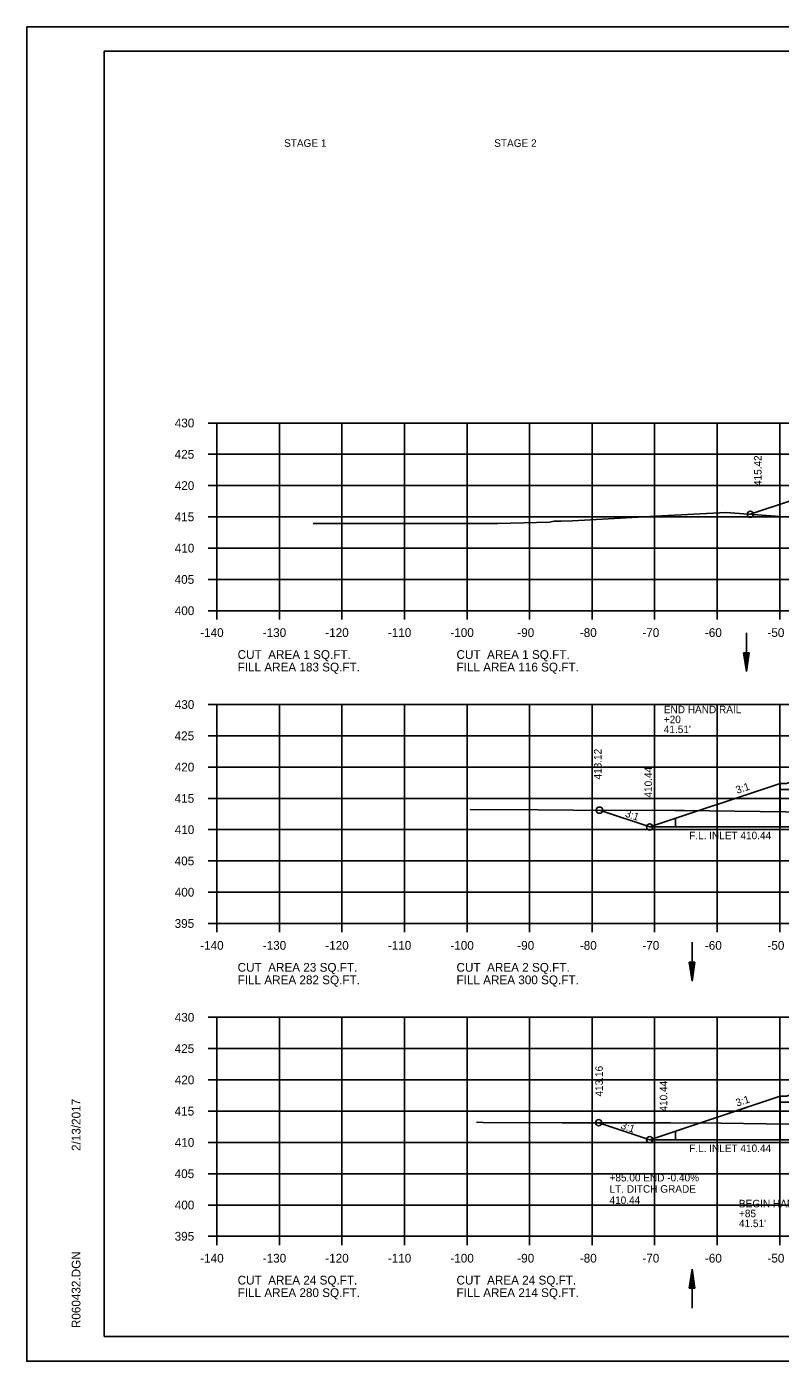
# Model space of a CAD drawing. Extents: x 1538688 to 1540766, y 656250 to 671912.
# Drawn here: x 1538687.8 to 1538808.3, y 661884.7 to 662098 of the extents above; entities that cross this region are included whole.
import ezdxf

# ---------------------------------------------------------------- set-up
doc = ezdxf.new("R2010")
doc.units = 0
for name, color, linetype in [('15', 7, 'Continuous'), ('18', 7, 'Continuous'), ('20', 7, 'Continuous'), ('22', 7, 'Continuous'), ('26', 7, 'Continuous'), ('39', 7, 'Continuous'), ('40', 7, 'Continuous'), ('41', 7, 'Continuous'), ('42', 7, 'Continuous'), ('7', 7, 'Continuous'), ('Borings', 7, 'Continuous'), ('Default', 7, 'Continuous'), ('Horizontal Alignment', 7, 'Continuous'), ('RipRap', 7, 'Continuous')]:
    doc.layers.add(name, color=color, linetype=linetype)

msp = doc.modelspace()

# ---------------------------------------------------------------- linework, layer by layer
at = {"layer": '15'}
for p, q in [((1538802.4, 661997.94), (1538802.85, 661994.94)), ((1538802.4, 661997.94), (1538803.3, 661997.94)), ((1538802.48, 661997.94), (1538802.85, 661995.44)), ((1538802.55, 661997.94), (1538802.85, 661995.95)), ((1538802.63, 661997.94), (1538802.85, 661996.45)), ((1538802.71, 661997.94), (1538802.85, 661996.96)), ((1538802.78, 661997.94), (1538802.85, 661997.46)), ((1538803.3, 661997.94), (1538802.85, 661994.94)), ((1538803, 661997.94), (1538802.85, 661996.96)), ((1538803.15, 661997.94), (1538802.85, 661995.95)), ((1538803.23, 661997.94), (1538802.85, 661995.44)), ((1538803.08, 661997.94), (1538802.85, 661996.45)), ((1538802.92, 661997.94), (1538802.85, 661997.46)), ((1538793.72, 661948.47), (1538794.17, 661945.47)), ((1538793.72, 661948.47), (1538794.62, 661948.47)), ((1538793.79, 661948.47), (1538794.17, 661945.97)), ((1538793.87, 661948.47), (1538794.17, 661946.49)), ((1538793.94, 661948.47), (1538794.17, 661946.99)), ((1538794.02, 661948.47), (1538794.17, 661947.5)), ((1538794.1, 661948.47), (1538794.17, 661948)), ((1538794.62, 661948.47), (1538794.17, 661945.47)), ((1538794.31, 661948.47), (1538794.17, 661947.5)), ((1538794.47, 661948.47), (1538794.17, 661946.49)), ((1538794.54, 661948.47), (1538794.17, 661945.97)), ((1538794.39, 661948.47), (1538794.17, 661946.99)), ((1538794.24, 661948.47), (1538794.17, 661948)), ((1538793.72, 661896.39), (1538794.17, 661899.39)), ((1538794.62, 661896.39), (1538794.17, 661899.39)), ((1538793.79, 661896.39), (1538794.17, 661898.89)), ((1538793.87, 661896.39), (1538794.17, 661898.37)), ((1538793.94, 661896.39), (1538794.17, 661897.87)), ((1538794.02, 661896.39), (1538794.17, 661897.36)), ((1538794.54, 661896.39), (1538794.17, 661898.89)), ((1538794.47, 661896.39), (1538794.17, 661898.37)), ((1538794.39, 661896.39), (1538794.17, 661897.87)), ((1538794.31, 661896.39), (1538794.17, 661897.36)), ((1538793.72, 661896.39), (1538794.62, 661896.39)), ((1538794.1, 661896.39), (1538794.17, 661896.86)), ((1538794.24, 661896.39), (1538794.17, 661896.86))]:
    msp.add_line(p, q, dxfattribs=at)
at = {"layer": '18'}
for points in [[(1538733.59, 662018.63), (1538763.11, 662018.59), (1538771.35, 662018.84), (1538772.12, 662018.97), (1538773.22, 662018.99), (1538775.05, 662019.04), (1538789.33, 662019.82), (1538799.55, 662020.38), (1538810.37, 662019.58)], [(1538758.7, 661972.89), (1538769.57, 661972.84), (1538775.13, 661972.81), (1538791.41, 661972.74), (1538791.55, 661972.74), (1538791.69, 661972.74), (1538791.98, 661972.74), (1538792.88, 661972.72), (1538821.26, 661972.36)], [(1538787.4, 661920.11), (1538808.28, 661927.07)], [(1538759.69, 661922.89), (1538760.76, 661922.88), (1538773.37, 661922.81), (1538778.56, 661922.83), (1538790.71, 661922.79), (1538798.76, 661922.74), (1538816.85, 661922.51)]]:
    msp.add_lwpolyline(points, dxfattribs=at)
at = {"layer": '20'}
for points in [[(1538803.48, 662020.09), (1538816.67, 662024.49), (1538821.67, 662024.39), (1538824.67, 662024.33), (1538825.17, 662024.33), (1538825.18, 662023.83), (1538826.18, 662023.85), (1538858.18, 662023.61), (1538890.18, 662022.97), (1538891.18, 662022.95), (1538891.19, 662023.45), (1538891.69, 662023.45), (1538894.69, 662023.51), (1538899.69, 662023.61), (1538911.32, 662019.73)], [(1538779.37, 661972.79), (1538787.4, 661970.11), (1538808.28, 661977.07), (1538809.28, 661977.07), (1538816.67, 661979.53), (1538821.67, 661979.43), (1538824.67, 661979.37), (1538825.17, 661979.37), (1538825.18, 661978.87), (1538826.18, 661978.89), (1538858.18, 661979.13), (1538890.18, 661978.49), (1538891.18, 661978.47), (1538891.19, 661978.97), (1538891.69, 661978.97), (1538894.69, 661979.03), (1538899.69, 661979.13), (1538912.11, 661975.02), (1538913.11, 661975.02), (1538934.55, 661967.88)], [(1538779.25, 661922.83), (1538787.4, 661920.11), (1538808.28, 661927.07), (1538809.28, 661927.07), (1538816.67, 661929.53), (1538821.67, 661929.43), (1538824.67, 661929.37), (1538825.17, 661929.37), (1538825.18, 661928.87), (1538826.18, 661928.89), (1538858.18, 661929.17), (1538890.18, 661928.53), (1538891.18, 661928.51), (1538891.19, 661929.01), (1538891.69, 661929.01), (1538894.69, 661929.07), (1538899.69, 661929.17), (1538912.11, 661925.02), (1538913.11, 661925.02), (1538933.99, 661918.07), (1538945.86, 661922.02)]]:
    msp.add_lwpolyline(points, dxfattribs=at)
at = {"layer": '22'}
for p, q in [((1538718.18, 662034.67), (1538998.18, 662034.67)), ((1538718.18, 662004.67), (1538718.18, 662034.67)), ((1538728.18, 662004.67), (1538728.18, 662034.67)), ((1538738.18, 662004.67), (1538738.18, 662034.67)), ((1538748.18, 662004.67), (1538748.18, 662034.67)), ((1538758.18, 662004.67), (1538758.18, 662034.67)), ((1538768.18, 662004.67), (1538768.18, 662034.67)), ((1538778.18, 662004.67), (1538778.18, 662034.67)), ((1538788.18, 662004.67), (1538788.18, 662034.67)), ((1538798.18, 662004.67), (1538798.18, 662034.67)), ((1538808.18, 662004.67), (1538808.18, 662034.67)), ((1538718.18, 662029.67), (1538998.18, 662029.67)), ((1538718.18, 662024.67), (1538998.18, 662024.67)), ((1538718.18, 662019.67), (1538998.18, 662019.67)), ((1538718.18, 662014.67), (1538998.18, 662014.67)), ((1538718.18, 662009.67), (1538998.18, 662009.67)), ((1538718.18, 662004.67), (1538998.18, 662004.67)), ((1538718.18, 661989.67), (1538998.18, 661989.67)), ((1538718.18, 661954.67), (1538718.18, 661989.67)), ((1538728.18, 661954.67), (1538728.18, 661989.67)), ((1538738.18, 661954.67), (1538738.18, 661989.67)), ((1538748.18, 661954.67), (1538748.18, 661989.67)), ((1538758.18, 661954.67), (1538758.18, 661989.67)), ((1538768.18, 661954.67), (1538768.18, 661989.67)), ((1538778.18, 661954.67), (1538778.18, 661989.67)), ((1538788.18, 661954.67), (1538788.18, 661989.67)), ((1538798.18, 661954.67), (1538798.18, 661989.67)), ((1538808.18, 661954.67), (1538808.18, 661989.67)), ((1538718.18, 661984.67), (1538998.18, 661984.67)), ((1538718.18, 661979.67), (1538998.18, 661979.67)), ((1538718.18, 661974.67), (1538998.18, 661974.67)), ((1538718.18, 661969.67), (1538998.18, 661969.67)), ((1538718.18, 661964.67), (1538998.18, 661964.67)), ((1538718.18, 661959.67), (1538998.18, 661959.67)), ((1538718.18, 661954.67), (1538998.18, 661954.67)), ((1538718.18, 661939.67), (1538998.18, 661939.67)), ((1538718.18, 661904.67), (1538718.18, 661939.67)), ((1538728.18, 661904.67), (1538728.18, 661939.67)), ((1538738.18, 661904.67), (1538738.18, 661939.67)), ((1538748.18, 661904.67), (1538748.18, 661939.67)), ((1538758.18, 661904.67), (1538758.18, 661939.67)), ((1538768.18, 661904.67), (1538768.18, 661939.67)), ((1538778.18, 661904.67), (1538778.18, 661939.67)), ((1538788.18, 661904.67), (1538788.18, 661939.67)), ((1538798.18, 661904.67), (1538798.18, 661939.67)), ((1538808.18, 661904.67), (1538808.18, 661939.67)), ((1538718.18, 661934.67), (1538998.18, 661934.67)), ((1538718.18, 661929.67), (1538998.18, 661929.67)), ((1538718.18, 661924.67), (1538998.18, 661924.67)), ((1538718.18, 661919.67), (1538998.18, 661919.67)), ((1538718.18, 661914.67), (1538998.18, 661914.67)), ((1538718.18, 661909.67), (1538998.18, 661909.67)), ((1538718.18, 661904.67), (1538998.18, 661904.67))]:
    msp.add_line(p, q, dxfattribs=at)
at = {"layer": '26'}
for p, q in [((1538687.78, 662098.02), (1539021.11, 662098.02)), ((1538687.78, 661884.69), (1539021.11, 661884.69))]:
    msp.add_line(p, q, dxfattribs=at)
msp.add_lwpolyline([(1538687.77, 662098.02), (1539021.11, 662098.02), (1539021.11, 661884.69), (1538687.77, 661884.69)], close=True, dxfattribs=at)
for centre in [(1538803.48, 662020.09), (1538779.37, 661972.79), (1538787.4, 661970.11), (1538779.25, 661922.83), (1538787.4, 661920.11)]:
    msp.add_circle(centre, 0.5, dxfattribs=at)
at = {"layer": '39'}
for p, q in [((1538802.85, 662001.12), (1538802.85, 661994.94)), ((1538808.28, 661977.07), (1538808.28, 661970.11)), ((1538808.28, 661977.07), (1538809.28, 661977.07)), ((1538808.28, 661976.11), (1538851.23, 661976.11)), ((1538787.4, 661970.11), (1538851.23, 661970.11)), ((1538791.53, 661971.48), (1538791.53, 661970.11)), ((1538794.17, 661951.66), (1538794.17, 661945.47)), ((1538808.28, 661927.07), (1538791.53, 661921.48)), ((1538808.28, 661927.07), (1538809.28, 661927.07)), ((1538808.28, 661927.07), (1538808.28, 661920.11)), ((1538808.28, 661926.11), (1538851.23, 661926.11)), ((1538791.53, 661921.48), (1538791.53, 661920.11)), ((1538787.4, 661920.11), (1538851.23, 661920.11)), ((1538794.17, 661893.2), (1538794.17, 661899.39))]:
    msp.add_line(p, q, dxfattribs=at)
at = {"layer": 'Borings'}
for p, q in [((1538716.78, 662034.67), (1538718.18, 662034.67)), ((1538718.18, 662004.67), (1538718.18, 662034.67)), ((1538716.78, 662029.67), (1538718.18, 662029.67)), ((1538716.78, 662024.67), (1538718.18, 662024.67)), ((1538716.78, 662019.67), (1538718.18, 662019.67)), ((1538716.78, 662014.67), (1538718.18, 662014.67)), ((1538716.78, 662009.67), (1538718.18, 662009.67)), ((1538716.78, 662004.67), (1538718.18, 662004.67)), ((1538718.18, 662004.67), (1538998.18, 662004.67)), ((1538718.18, 662003.27), (1538718.18, 662004.67)), ((1538728.18, 662003.27), (1538728.18, 662004.67)), ((1538738.18, 662003.27), (1538738.18, 662004.67)), ((1538748.18, 662003.27), (1538748.18, 662004.67)), ((1538758.18, 662003.27), (1538758.18, 662004.67)), ((1538768.18, 662003.27), (1538768.18, 662004.67)), ((1538778.18, 662003.27), (1538778.18, 662004.67)), ((1538788.18, 662003.27), (1538788.18, 662004.67)), ((1538798.18, 662003.27), (1538798.18, 662004.67)), ((1538808.18, 662003.27), (1538808.18, 662004.67)), ((1538716.78, 661989.67), (1538718.18, 661989.67)), ((1538718.18, 661954.67), (1538718.18, 661989.67)), ((1538716.78, 661984.67), (1538718.18, 661984.67)), ((1538716.78, 661979.67), (1538718.18, 661979.67)), ((1538716.78, 661974.67), (1538718.18, 661974.67)), ((1538716.78, 661969.67), (1538718.18, 661969.67)), ((1538716.78, 661964.67), (1538718.18, 661964.67)), ((1538716.78, 661959.67), (1538718.18, 661959.67)), ((1538716.78, 661954.67), (1538718.18, 661954.67)), ((1538718.18, 661954.67), (1538998.18, 661954.67)), ((1538718.18, 661953.27), (1538718.18, 661954.67)), ((1538728.18, 661953.27), (1538728.18, 661954.67)), ((1538738.18, 661953.27), (1538738.18, 661954.67)), ((1538748.18, 661953.27), (1538748.18, 661954.67)), ((1538758.18, 661953.27), (1538758.18, 661954.67)), ((1538768.18, 661953.27), (1538768.18, 661954.67)), ((1538778.18, 661953.27), (1538778.18, 661954.67)), ((1538788.18, 661953.27), (1538788.18, 661954.67)), ((1538798.18, 661953.27), (1538798.18, 661954.67)), ((1538808.18, 661953.27), (1538808.18, 661954.67)), ((1538716.78, 661939.67), (1538718.18, 661939.67)), ((1538718.18, 661904.67), (1538718.18, 661939.67)), ((1538716.78, 661934.67), (1538718.18, 661934.67)), ((1538716.78, 661929.67), (1538718.18, 661929.67)), ((1538716.78, 661924.67), (1538718.18, 661924.67)), ((1538716.78, 661919.67), (1538718.18, 661919.67)), ((1538716.78, 661914.67), (1538718.18, 661914.67)), ((1538716.78, 661909.67), (1538718.18, 661909.67)), ((1538716.78, 661904.67), (1538718.18, 661904.67)), ((1538718.18, 661904.67), (1538998.18, 661904.67)), ((1538718.18, 661903.27), (1538718.18, 661904.67)), ((1538728.18, 661903.27), (1538728.18, 661904.67)), ((1538738.18, 661903.27), (1538738.18, 661904.67)), ((1538748.18, 661903.27), (1538748.18, 661904.67)), ((1538758.18, 661903.27), (1538758.18, 661904.67)), ((1538768.18, 661903.27), (1538768.18, 661904.67)), ((1538778.18, 661903.27), (1538778.18, 661904.67)), ((1538788.18, 661903.27), (1538788.18, 661904.67)), ((1538798.18, 661903.27), (1538798.18, 661904.67)), ((1538808.18, 661903.27), (1538808.18, 661904.67))]:
    msp.add_line(p, q, dxfattribs=at)
at = {"layer": 'RipRap'}
for p, q in [((1538700.18, 662094.13), (1539016.36, 662094.13)), ((1538700.18, 661888.67), (1538700.18, 662094.13)), ((1538700.18, 661888.67), (1538700.18, 661888.67)), ((1539016.36, 661888.67), (1538700.18, 661888.67))]:
    msp.add_line(p, q, dxfattribs=at)

# ---------------------------------------------------------------- texts
at = {"layer": '39'}
for p in [(1538793.7, 661968.14), (1538793.7, 661918.14)]:
    msp.add_text('F.L. INLET 410.44', height=1.2, dxfattribs=at).set_placement(p)
at = {"layer": '40'}
for s, p in [('+85.00 END -0.40%', (1538780.97, 661913.44)), ('LT. DITCH GRADE', (1538780.97, 661911.64)), ('410.44', (1538780.97, 661909.84))]:
    msp.add_text(s, height=1.2, dxfattribs=at).set_placement(p)
at = {"layer": '41'}
for s, p in [('415.42', (1538805.28, 662024.59)), ('413.12', (1538779.69, 661977.69)), ('410.44', (1538787.76, 661974.8)), ('413.16', (1538779.9, 661927.01)), ('410.44', (1538790.2, 661924.61))]:
    msp.add_text(s, height=1.2, rotation=90, dxfattribs=at).set_placement(p)
at = {"layer": '42'}
for rotation, p in [(18.4349, (1538801.38, 661975.39)), (341.5651, (1538783.35, 661971.78)), (18.4349, (1538801.38, 661925.39)), (341.5651, (1538782.67, 661921.91))]:
    msp.add_text('3:1', height=1.2, rotation=rotation, dxfattribs=at).set_placement(p)
at = {"layer": '7'}
for s, p in [('END HAND RAIL', (1538789.65, 661988.28)), ('+20', (1538789.65, 661986.69)), ("41.51'", (1538789.65, 661985.11)), ('BEGIN HAND RAIL', (1538801.67, 661909.3)), ('+85', (1538801.67, 661907.72)), ("41.51'", (1538801.67, 661906.13))]:
    msp.add_text(s, height=1.2, dxfattribs=at).set_placement(p)
at = {"layer": 'Default'}
for s, p in [('STAGE 1', (1538728.93, 662078.82)), ('STAGE 2', (1538762.53, 662078.82))]:
    msp.add_text(s, height=1.2, dxfattribs=at).set_placement(p)
at = {"layer": 'Horizontal Alignment'}
for s, p in [('430', (1538711.45, 662033.97)), ('425', (1538711.43, 662028.97)), ('420', (1538711.45, 662023.97)), ('415', (1538711.43, 662018.97)), ('410', (1538711.45, 662013.97)), ('405', (1538711.43, 662008.97)), ('400', (1538711.45, 662003.97)), ('-140', (1538715.52, 662000.47)), ('-130', (1538725.52, 662000.47)), ('-120', (1538735.52, 662000.47)), ('-110', (1538745.52, 662000.47)), ('-100', (1538755.52, 662000.47)), ('-90', (1538766.22, 662000.47)), ('-80', (1538776.22, 662000.47)), ('-70', (1538786.22, 662000.47)), ('-60', (1538796.22, 662000.47)), ('-50', (1538806.22, 662000.47)), ('CUT  AREA 1 SQ.FT.', (1538721.5, 661996.96)), ('CUT  AREA 1 SQ.FT.', (1538756.5, 661996.96)), ('FILL AREA 183 SQ.FT.', (1538721.5, 661994.96)), ('FILL AREA 116 SQ.FT.', (1538756.5, 661994.96)), ('430', (1538711.45, 661988.97)), ('425', (1538711.43, 661983.97)), ('420', (1538711.45, 661978.97)), ('415', (1538711.43, 661973.97)), ('410', (1538711.45, 661968.97)), ('405', (1538711.43, 661963.97)), ('400', (1538711.45, 661958.97)), ('395', (1538711.43, 661953.97)), ('-140', (1538715.52, 661950.47)), ('-130', (1538725.52, 661950.47)), ('-120', (1538735.52, 661950.47)), ('-110', (1538745.52, 661950.47)), ('-100', (1538755.52, 661950.47)), ('-90', (1538766.22, 661950.47)), ('-80', (1538776.22, 661950.47)), ('-70', (1538786.22, 661950.47)), ('-60', (1538796.22, 661950.47)), ('-50', (1538806.22, 661950.47)), ('CUT  AREA 23 SQ.FT.', (1538721.5, 661946.96)), ('CUT  AREA 2 SQ.FT.', (1538756.5, 661946.96)), ('FILL AREA 282 SQ.FT.', (1538721.5, 661944.96)), ('FILL AREA 300 SQ.FT.', (1538756.5, 661944.96)), ('430', (1538711.45, 661938.97)), ('425', (1538711.43, 661933.97)), ('420', (1538711.45, 661928.97)), ('415', (1538711.43, 661923.97)), ('410', (1538711.45, 661918.97)), ('405', (1538711.43, 661913.97)), ('400', (1538711.45, 661908.97)), ('395', (1538711.43, 661903.97)), ('-140', (1538715.52, 661900.47)), ('-130', (1538725.52, 661900.47)), ('-120', (1538735.52, 661900.47)), ('-110', (1538745.52, 661900.47)), ('-100', (1538755.52, 661900.47)), ('-90', (1538766.22, 661900.47)), ('-80', (1538776.22, 661900.47)), ('-70', (1538786.22, 661900.47)), ('-60', (1538796.22, 661900.47)), ('-50', (1538806.22, 661900.47)), ('CUT  AREA 24 SQ.FT.', (1538721.5, 661896.96)), ('CUT  AREA 24 SQ.FT.', (1538756.5, 661896.96)), ('FILL AREA 280 SQ.FT.', (1538721.5, 661894.96)), ('FILL AREA 214 SQ.FT.', (1538756.5, 661894.96))]:
    msp.add_text(s, height=1.4, dxfattribs=at).set_placement(p)
at = {"layer": 'RipRap'}
for s, p in [('2/13/2017', (1538696.37, 661918.31)), ('R060432.DGN', (1538696.37, 661889.99))]:
    msp.add_text(s, height=1.4, rotation=90, dxfattribs=at).set_placement(p)

doc.saveas('drawing.dxf')
